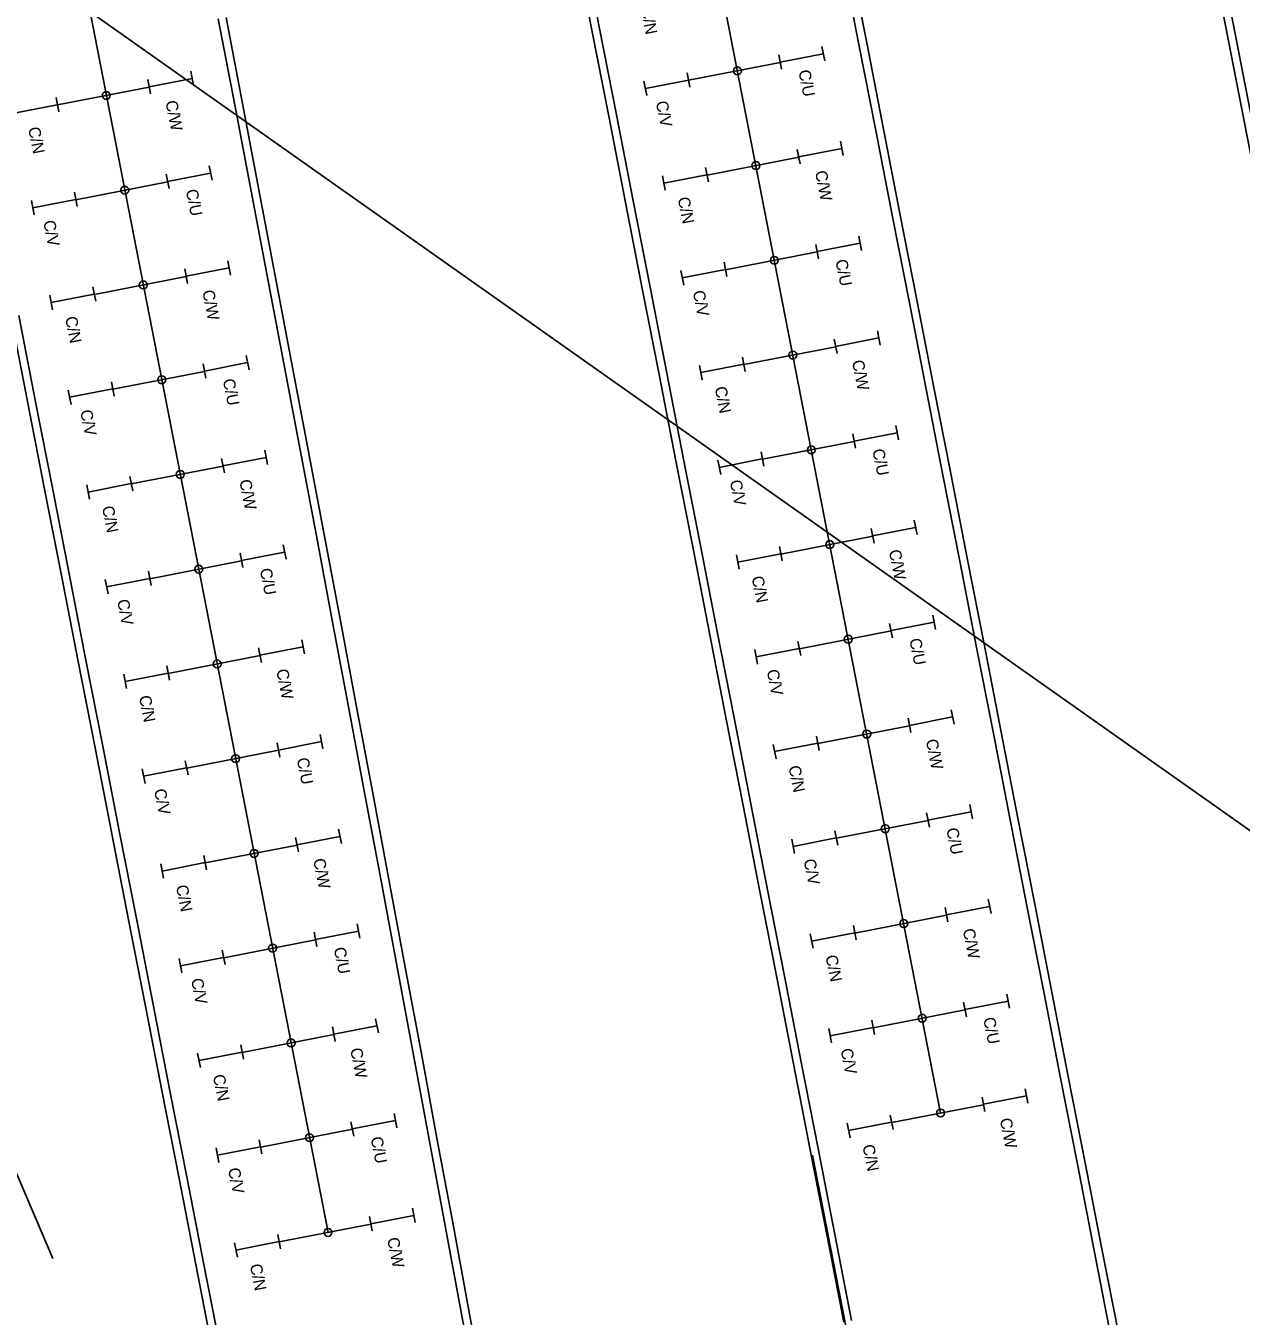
# Model space of a CAD drawing. Extents: x -545258 to -544992, y -1122311 to -1121664.
# Drawn here: x -545181.96 to -545154.28, y -1121960 to -1121930.59 of the extents above; entities that cross this region are included whole.
import ezdxf

# ---------------------------------------------------------------- set-up
doc = ezdxf.new("R2010")
doc.units = 0
for name, color, linetype in [('SO18-15-04', 7, 'Continuous'), ('SO18-15-08', 7, 'Continuous'), ('SO18-16-02', 7, 'Continuous'), ('so180605', 7, 'Continuous'), ('SOPS', 7, 'Continuous')]:
    doc.layers.add(name, color=color, linetype=linetype)

msp = doc.modelspace()

# ---------------------------------------------------------------- linework, layer by layer
at = {"layer": 'SO18-15-04'}
for centre in [(-545165.753, -1121931.617), (-545180.131, -1121932.179), (-545165.332, -1121933.777), (-545179.71, -1121934.338), (-545164.911, -1121935.936), (-545179.289, -1121936.498), (-545164.49, -1121938.095), (-545178.868, -1121938.657), (-545164.069, -1121940.255), (-545178.447, -1121940.816), (-545163.648, -1121942.414), (-545178.026, -1121942.976), (-545163.227, -1121944.573), (-545177.605, -1121945.135), (-545162.806, -1121946.733), (-545177.185, -1121947.294), (-545162.385, -1121948.892), (-545176.764, -1121949.454), (-545161.964, -1121951.052), (-545176.343, -1121951.613), (-545161.544, -1121953.211), (-545175.922, -1121953.773), (-545161.123, -1121955.37), (-545175.501, -1121955.932), (-545175.08, -1121958.091)]:
    msp.add_circle(centre, 0.09, dxfattribs=at)
at = {"layer": 'SO18-16-02'}
for points in [[(-545152.977, -1121939.071), (-545158.305, -1121911.735), (-545158.688, -1121909.772), (-545159.071, -1121907.809), (-545159.453, -1121905.846), (-545159.836, -1121903.883), (-545160.219, -1121901.92), (-545160.601, -1121899.957), (-545160.984, -1121897.994), (-545161.367, -1121896.031), (-545161.749, -1121894.068), (-545162.132, -1121892.105), (-545162.514, -1121890.142), (-545162.897, -1121888.179), (-545163.28, -1121886.216), (-545163.662, -1121884.253), (-545164.045, -1121882.29), (-545164.428, -1121880.326), (-545164.81, -1121878.363), (-545165.193, -1121876.4), (-545165.375, -1121875.468)], [(-545152.801, -1121939.037), (-545158.129, -1121911.701), (-545158.511, -1121909.738), (-545158.894, -1121907.775), (-545159.277, -1121905.812), (-545159.659, -1121903.849), (-545160.042, -1121901.886), (-545160.425, -1121899.923), (-545160.807, -1121897.96), (-545161.19, -1121895.997), (-545161.572, -1121894.033), (-545161.955, -1121892.07), (-545162.338, -1121890.107), (-545162.72, -1121888.144), (-545163.103, -1121886.181), (-545163.486, -1121884.218), (-545163.868, -1121882.255), (-545164.251, -1121880.292), (-545164.634, -1121878.329), (-545165.016, -1121876.366), (-545165.198, -1121875.433)], [(-545167.92, -1121936.579), (-545168.302, -1121934.616), (-545168.685, -1121932.653), (-545169.068, -1121930.69), (-545169.45, -1121928.727)], [(-545167.743, -1121936.545), (-545168.126, -1121934.582), (-545168.508, -1121932.619), (-545168.891, -1121930.656), (-545169.273, -1121928.693)], [(-545163.365, -1121929.054), (-545162.983, -1121931.017), (-545162.6, -1121932.98), (-545162.217, -1121934.943), (-545161.835, -1121936.906), (-545161.452, -1121938.869), (-545161.069, -1121940.832), (-545160.687, -1121942.795), (-545160.304, -1121944.758), (-545159.921, -1121946.721), (-545159.539, -1121948.685), (-545159.156, -1121950.648), (-545158.773, -1121952.611), (-545158.391, -1121954.574), (-545158.008, -1121956.537), (-545157.625, -1121958.5), (-545157.243, -1121960.463)], [(-545163.189, -1121929.02), (-545162.806, -1121930.983), (-545162.423, -1121932.946), (-545162.041, -1121934.909), (-545161.658, -1121936.872), (-545161.275, -1121938.835), (-545160.893, -1121940.798), (-545160.51, -1121942.761), (-545160.127, -1121944.724), (-545159.745, -1121946.687), (-545159.362, -1121948.65), (-545158.979, -1121950.613), (-545158.597, -1121952.576), (-545158.214, -1121954.539), (-545157.831, -1121956.502), (-545157.449, -1121958.465), (-545157.066, -1121960.428)], [(-545176.655, -1121934.327), (-545177.029, -1121932.363), (-545177.403, -1121930.399)], [(-545176.832, -1121934.361), (-545177.206, -1121932.396), (-545177.58, -1121930.433)], [(-545171.683, -1121961.872), (-545172.046, -1121959.906), (-545172.409, -1121957.94), (-545172.773, -1121955.974), (-545173.138, -1121954.009), (-545173.504, -1121952.043), (-545173.871, -1121950.078), (-545174.238, -1121948.113), (-545174.606, -1121946.148), (-545174.975, -1121944.183), (-545175.345, -1121942.218), (-545175.715, -1121940.253), (-545176.087, -1121938.289), (-545176.459, -1121936.325), (-545176.832, -1121934.36)], [(-545171.506, -1121961.84), (-545171.869, -1121959.874), (-545172.232, -1121957.908), (-545172.597, -1121955.942), (-545172.961, -1121953.976), (-545173.327, -1121952.01), (-545173.694, -1121950.045), (-545174.061, -1121948.08), (-545174.429, -1121946.114), (-545174.798, -1121944.149), (-545175.168, -1121942.185), (-545175.539, -1121940.22), (-545175.91, -1121938.255), (-545176.282, -1121936.291), (-545176.655, -1121934.327)], [(-545163.328, -1121960.136), (-545163.71, -1121958.173), (-545164.093, -1121956.21), (-545164.476, -1121954.247), (-545164.858, -1121952.284), (-545165.241, -1121950.321), (-545165.624, -1121948.358), (-545166.006, -1121946.395), (-545166.389, -1121944.431), (-545166.772, -1121942.468), (-545167.154, -1121940.505), (-545167.537, -1121938.542), (-545167.92, -1121936.579)], [(-545163.151, -1121960.101), (-545163.534, -1121958.138), (-545163.916, -1121956.175), (-545164.299, -1121954.212), (-545164.682, -1121952.249), (-545165.064, -1121950.286), (-545165.447, -1121948.323), (-545165.83, -1121946.36), (-545166.212, -1121944.397), (-545166.595, -1121942.434), (-545166.978, -1121940.471), (-545167.36, -1121938.508), (-545167.743, -1121936.545)], [(-545182.301, -1121937.229), (-545181.918, -1121939.192), (-545181.536, -1121941.155), (-545181.153, -1121943.118), (-545180.77, -1121945.081), (-545180.388, -1121947.044), (-545180.005, -1121949.007), (-545179.622, -1121950.97), (-545179.24, -1121952.934), (-545178.857, -1121954.897), (-545178.474, -1121956.86), (-545178.092, -1121958.823), (-545177.709, -1121960.786)], [(-545182.124, -1121937.195), (-545181.742, -1121939.158), (-545181.359, -1121941.121), (-545180.976, -1121943.084), (-545180.594, -1121945.047), (-545180.211, -1121947.01), (-545179.828, -1121948.973), (-545179.446, -1121950.936), (-545179.063, -1121952.899), (-545178.68, -1121954.862), (-545178.298, -1121956.825), (-545177.915, -1121958.788), (-545177.532, -1121960.751)], [(-545164.044, -1121956.329), (-545162.131, -1121966.144), (-545160.218, -1121975.96), (-545158.438, -1121985.088)]]:
    msp.add_lwpolyline(points, dxfattribs=at)
at = {"layer": 'so180605'}
for p, q in [((-545164.809, -1121931.253), (-545164.745, -1121931.582)), ((-545164.778, -1121931.419), (-545163.797, -1121931.228)), ((-545163.827, -1121931.065), (-545163.763, -1121931.39)), ((-545179.187, -1121931.815), (-545179.123, -1121932.143)), ((-545179.156, -1121931.981), (-545178.175, -1121931.79)), ((-545178.205, -1121931.626), (-545178.142, -1121931.952)), ((-545167.881, -1121931.852), (-545167.817, -1121932.181)), ((-545167.85, -1121932.018), (-545166.869, -1121931.827)), ((-545166.899, -1121931.664), (-545166.836, -1121931.989)), ((-545182.229, -1121932.58), (-545181.247, -1121932.389)), ((-545181.277, -1121932.225), (-545181.214, -1121932.551)), ((-545163.406, -1121933.224), (-545163.343, -1121933.55)), ((-545164.388, -1121933.413), (-545164.324, -1121933.741)), ((-545164.357, -1121933.579), (-545163.376, -1121933.388)), ((-545177.784, -1121933.786), (-545177.721, -1121934.111)), ((-545166.478, -1121933.823), (-545166.415, -1121934.149)), ((-545178.766, -1121933.974), (-545178.702, -1121934.303)), ((-545178.735, -1121934.14), (-545177.754, -1121933.949)), ((-545167.46, -1121934.011), (-545167.396, -1121934.34)), ((-545167.429, -1121934.178), (-545166.448, -1121933.986)), ((-545180.857, -1121934.385), (-545180.793, -1121934.71)), ((-545181.839, -1121934.573), (-545181.775, -1121934.902)), ((-545181.808, -1121934.739), (-545180.826, -1121934.548)), ((-545162.985, -1121935.384), (-545162.922, -1121935.709)), ((-545163.967, -1121935.572), (-545163.903, -1121935.901)), ((-545163.936, -1121935.738), (-545162.955, -1121935.547)), ((-545177.363, -1121935.945), (-545177.3, -1121936.271)), ((-545166.057, -1121935.982), (-545165.994, -1121936.308)), ((-545178.345, -1121936.134), (-545178.281, -1121936.462)), ((-545178.315, -1121936.3), (-545177.333, -1121936.109)), ((-545167.039, -1121936.171), (-545166.975, -1121936.499)), ((-545167.008, -1121936.337), (-545166.027, -1121936.146)), ((-545180.436, -1121936.544), (-545180.372, -1121936.87)), ((-545181.418, -1121936.732), (-545181.354, -1121937.061)), ((-545181.387, -1121936.899), (-545180.405, -1121936.707)), ((-545163.546, -1121937.731), (-545163.482, -1121938.06)), ((-545163.515, -1121937.898), (-545162.534, -1121937.706)), ((-545162.564, -1121937.543), (-545162.501, -1121937.869)), ((-545177.925, -1121938.293), (-545177.861, -1121938.622)), ((-545177.894, -1121938.459), (-545176.912, -1121938.268)), ((-545176.942, -1121938.105), (-545176.879, -1121938.43)), ((-545166.618, -1121938.33), (-545166.554, -1121938.659)), ((-545166.588, -1121938.496), (-545165.606, -1121938.305)), ((-545165.636, -1121938.142), (-545165.573, -1121938.467)), ((-545180.997, -1121938.892), (-545180.933, -1121939.22)), ((-545180.966, -1121939.058), (-545179.984, -1121938.867)), ((-545180.015, -1121938.703), (-545179.951, -1121939.029)), ((-545162.143, -1121939.702), (-545162.08, -1121940.028)), ((-545163.125, -1121939.891), (-545163.061, -1121940.219)), ((-545163.094, -1121940.057), (-545162.113, -1121939.866)), ((-545176.522, -1121940.264), (-545176.458, -1121940.59)), ((-545165.215, -1121940.301), (-545165.152, -1121940.627)), ((-545177.504, -1121940.452), (-545177.44, -1121940.781)), ((-545177.473, -1121940.619), (-545176.491, -1121940.427)), ((-545166.198, -1121940.49), (-545166.134, -1121940.818)), ((-545166.167, -1121940.656), (-545165.185, -1121940.464)), ((-545179.594, -1121940.863), (-545179.53, -1121941.188)), ((-545180.576, -1121941.051), (-545180.512, -1121941.38)), ((-545180.545, -1121941.217), (-545179.563, -1121941.026)), ((-545161.722, -1121941.862), (-545161.659, -1121942.187)), ((-545162.704, -1121942.05), (-545162.64, -1121942.379)), ((-545162.674, -1121942.216), (-545161.692, -1121942.025)), ((-545176.101, -1121942.423), (-545176.037, -1121942.749)), ((-545164.795, -1121942.46), (-545164.731, -1121942.786)), ((-545177.083, -1121942.612), (-545177.019, -1121942.94)), ((-545177.052, -1121942.778), (-545176.07, -1121942.587)), ((-545165.777, -1121942.649), (-545165.713, -1121942.977)), ((-545165.746, -1121942.815), (-545164.764, -1121942.624)), ((-545179.173, -1121943.022), (-545179.109, -1121943.348)), ((-545180.155, -1121943.211), (-545180.091, -1121943.539)), ((-545180.124, -1121943.377), (-545179.142, -1121943.185)), ((-545162.284, -1121944.21), (-545162.219, -1121944.538)), ((-545162.253, -1121944.376), (-545161.271, -1121944.184)), ((-545161.301, -1121944.021), (-545161.238, -1121944.347)), ((-545176.662, -1121944.771), (-545176.598, -1121945.1)), ((-545176.631, -1121944.937), (-545175.649, -1121944.746)), ((-545175.68, -1121944.583), (-545175.616, -1121944.908)), ((-545165.356, -1121944.808), (-545165.292, -1121945.137)), ((-545165.325, -1121944.974), (-545164.343, -1121944.783)), ((-545164.374, -1121944.62), (-545164.31, -1121944.945)), ((-545179.734, -1121945.37), (-545179.67, -1121945.698)), ((-545179.703, -1121945.536), (-545178.722, -1121945.345)), ((-545178.752, -1121945.181), (-545178.688, -1121945.507)), ((-545160.881, -1121946.18), (-545160.817, -1121946.506)), ((-545161.863, -1121946.369), (-545161.799, -1121946.697)), ((-545161.832, -1121946.535), (-545160.85, -1121946.344)), ((-545175.259, -1121946.742), (-545175.195, -1121947.068)), ((-545163.953, -1121946.779), (-545163.889, -1121947.105)), ((-545176.241, -1121946.931), (-545176.177, -1121947.259)), ((-545176.21, -1121947.097), (-545175.228, -1121946.905)), ((-545164.935, -1121946.968), (-545164.871, -1121947.296)), ((-545164.904, -1121947.134), (-545163.922, -1121946.942)), ((-545178.331, -1121947.341), (-545178.268, -1121947.666)), ((-545179.313, -1121947.529), (-545179.249, -1121947.858)), ((-545179.282, -1121947.695), (-545178.301, -1121947.504)), ((-545160.46, -1121948.34), (-545160.396, -1121948.665)), ((-545161.442, -1121948.528), (-545161.378, -1121948.857)), ((-545161.411, -1121948.694), (-545160.429, -1121948.503)), ((-545174.838, -1121948.901), (-545174.774, -1121949.227)), ((-545163.532, -1121948.938), (-545163.468, -1121949.264)), ((-545175.82, -1121949.09), (-545175.756, -1121949.418)), ((-545175.789, -1121949.256), (-545174.808, -1121949.065)), ((-545164.514, -1121949.127), (-545164.45, -1121949.455)), ((-545164.483, -1121949.293), (-545163.501, -1121949.102)), ((-545177.91, -1121949.5), (-545177.847, -1121949.826)), ((-545178.892, -1121949.689), (-545178.828, -1121950.017)), ((-545178.861, -1121949.855), (-545177.88, -1121949.663)), ((-545161.021, -1121950.688), (-545160.957, -1121951.016)), ((-545160.99, -1121950.854), (-545160.008, -1121950.662)), ((-545160.039, -1121950.499), (-545159.975, -1121950.825)), ((-545175.399, -1121951.249), (-545175.335, -1121951.578)), ((-545175.368, -1121951.415), (-545174.387, -1121951.224)), ((-545174.417, -1121951.061), (-545174.353, -1121951.386)), ((-545164.093, -1121951.286), (-545164.029, -1121951.615)), ((-545164.062, -1121951.452), (-545163.081, -1121951.261)), ((-545163.111, -1121951.098), (-545163.047, -1121951.423)), ((-545178.471, -1121951.848), (-545178.407, -1121952.176)), ((-545178.44, -1121952.014), (-545177.459, -1121951.823)), ((-545177.489, -1121951.659), (-545177.426, -1121951.985)), ((-545159.618, -1121952.658), (-545159.554, -1121952.984)), ((-545160.6, -1121952.847), (-545160.536, -1121953.175)), ((-545160.569, -1121953.013), (-545159.587, -1121952.822)), ((-545173.996, -1121953.22), (-545173.933, -1121953.546)), ((-545162.69, -1121953.257), (-545162.626, -1121953.583)), ((-545174.978, -1121953.409), (-545174.914, -1121953.737)), ((-545174.947, -1121953.575), (-545173.966, -1121953.383)), ((-545163.672, -1121953.446), (-545163.608, -1121953.774)), ((-545163.641, -1121953.612), (-545162.66, -1121953.42)), ((-545183.485, -1121953.687), (-545181.35, -1121958.687)), ((-545177.068, -1121953.819), (-545177.005, -1121954.144)), ((-545178.05, -1121954.007), (-545177.986, -1121954.336)), ((-545178.019, -1121954.173), (-545177.038, -1121953.982)), ((-545159.197, -1121954.818), (-545159.133, -1121955.143)), ((-545160.179, -1121955.006), (-545160.115, -1121955.335)), ((-545160.148, -1121955.172), (-545159.166, -1121954.981)), ((-545173.575, -1121955.379), (-545173.512, -1121955.705)), ((-545174.557, -1121955.568), (-545174.493, -1121955.896)), ((-545174.526, -1121955.734), (-545173.545, -1121955.543)), ((-545163.251, -1121955.605), (-545163.187, -1121955.933)), ((-545163.22, -1121955.771), (-545162.239, -1121955.58)), ((-545162.269, -1121955.416), (-545162.206, -1121955.742)), ((-545176.647, -1121955.978), (-545176.584, -1121956.304)), ((-545177.629, -1121956.167), (-545177.565, -1121956.495)), ((-545177.598, -1121956.333), (-545176.617, -1121956.141)), ((-545174.136, -1121957.727), (-545174.072, -1121958.056)), ((-545174.105, -1121957.893), (-545173.124, -1121957.702)), ((-545173.154, -1121957.539), (-545173.091, -1121957.864)), ((-545177.208, -1121958.326), (-545177.144, -1121958.654)), ((-545177.178, -1121958.492), (-545176.196, -1121958.301)), ((-545176.226, -1121958.137), (-545176.163, -1121958.463))]:
    msp.add_line(p, q, dxfattribs=at)
for points in [[(-545198.555, -1121763.356), (-545161.123, -1121955.37)], [(-545212.512, -1121766.077), (-545175.08, -1121958.091)], [(-545166.866, -1121931.834), (-545164.775, -1121931.427)], [(-545181.244, -1121932.395), (-545179.153, -1121931.988)], [(-545166.445, -1121933.993), (-545164.354, -1121933.586)], [(-545180.823, -1121934.555), (-545178.733, -1121934.148)], [(-545166.024, -1121936.152), (-545163.933, -1121935.745)], [(-545180.402, -1121936.714), (-545178.312, -1121936.307)], [(-545165.603, -1121938.312), (-545163.512, -1121937.905)], [(-545179.981, -1121938.873), (-545177.891, -1121938.467)], [(-545165.182, -1121940.471), (-545163.092, -1121940.064)], [(-545179.561, -1121941.033), (-545177.47, -1121940.626)], [(-545164.761, -1121942.631), (-545162.671, -1121942.224)], [(-545179.14, -1121943.192), (-545177.049, -1121942.785)], [(-545164.34, -1121944.79), (-545162.25, -1121944.383)], [(-545178.719, -1121945.352), (-545176.628, -1121944.945)], [(-545163.92, -1121946.949), (-545161.829, -1121946.542)], [(-545178.298, -1121947.511), (-545176.207, -1121947.104)], [(-545163.499, -1121949.109), (-545161.408, -1121948.702)], [(-545177.877, -1121949.67), (-545175.786, -1121949.263)], [(-545163.078, -1121951.268), (-545160.987, -1121950.861)], [(-545177.456, -1121951.83), (-545175.365, -1121951.423)], [(-545162.657, -1121953.427), (-545160.566, -1121953.02)], [(-545177.035, -1121953.989), (-545174.944, -1121953.582)], [(-545162.236, -1121955.587), (-545160.145, -1121955.18)], [(-545176.614, -1121956.148), (-545174.523, -1121955.741)], [(-545176.193, -1121958.308), (-545174.102, -1121957.901)]]:
    msp.add_lwpolyline(points, dxfattribs=at)
at = {"layer": 'SOPS'}
msp.add_line((-545100.371, -1121986.851), (-545195.929, -1121919.376), dxfattribs=at)

# ---------------------------------------------------------------- texts
at = {"layer": 'SO18-15-08'}
for s, p in [('C/N', (-545167.956, -1121930.201)), ('C/U', (-545164.363, -1121931.62)), ('C/W', (-545178.785, -1121932.319)), ('C/V', (-545167.612, -1121932.329)), ('C/N', (-545181.913, -1121932.922)), ('C/W', (-545163.986, -1121933.916)), ('C/U', (-545178.32, -1121934.341)), ('C/N', (-545167.114, -1121934.519)), ('C/V', (-545181.569, -1121935.05)), ('C/U', (-545163.521, -1121935.939)), ('C/W', (-545177.944, -1121936.637)), ('C/V', (-545166.77, -1121936.647)), ('C/N', (-545181.071, -1121937.24)), ('C/W', (-545163.144, -1121938.235)), ('C/U', (-545177.478, -1121938.66)), ('C/N', (-545166.272, -1121938.838)), ('C/V', (-545180.727, -1121939.368)), ('C/U', (-545162.679, -1121940.258)), ('C/W', (-545177.102, -1121940.956)), ('C/V', (-545165.928, -1121940.966)), ('C/N', (-545180.23, -1121941.559)), ('C/W', (-545162.303, -1121942.554)), ('C/U', (-545176.636, -1121942.979)), ('C/N', (-545165.43, -1121943.157)), ('C/V', (-545179.886, -1121943.687)), ('C/U', (-545161.837, -1121944.576)), ('C/W', (-545176.26, -1121945.275)), ('C/V', (-545165.086, -1121945.285)), ('C/N', (-545179.388, -1121945.878)), ('C/W', (-545161.461, -1121946.873)), ('C/U', (-545175.794, -1121947.297)), ('C/N', (-545164.589, -1121947.476)), ('C/V', (-545179.044, -1121948.006)), ('C/U', (-545160.995, -1121948.895)), ('C/W', (-545175.418, -1121949.594)), ('C/V', (-545164.245, -1121949.604)), ('C/N', (-545178.546, -1121950.197)), ('C/W', (-545160.619, -1121951.191)), ('C/U', (-545174.952, -1121951.616)), ('C/N', (-545163.747, -1121951.794)), ('C/V', (-545178.202, -1121952.325)), ('C/U', (-545160.153, -1121953.214)), ('C/W', (-545174.576, -1121953.912)), ('C/V', (-545163.403, -1121953.922)), ('C/N', (-545177.704, -1121954.515)), ('C/W', (-545159.777, -1121955.51)), ('C/U', (-545174.111, -1121955.935)), ('C/N', (-545162.905, -1121956.113)), ('C/V', (-545177.36, -1121956.643)), ('C/W', (-545173.734, -1121958.231)), ('C/N', (-545176.862, -1121958.834))]:
    msp.add_text(s, height=0.2688, rotation=281.121, dxfattribs=at).set_placement(p)

doc.saveas('drawing.dxf')
